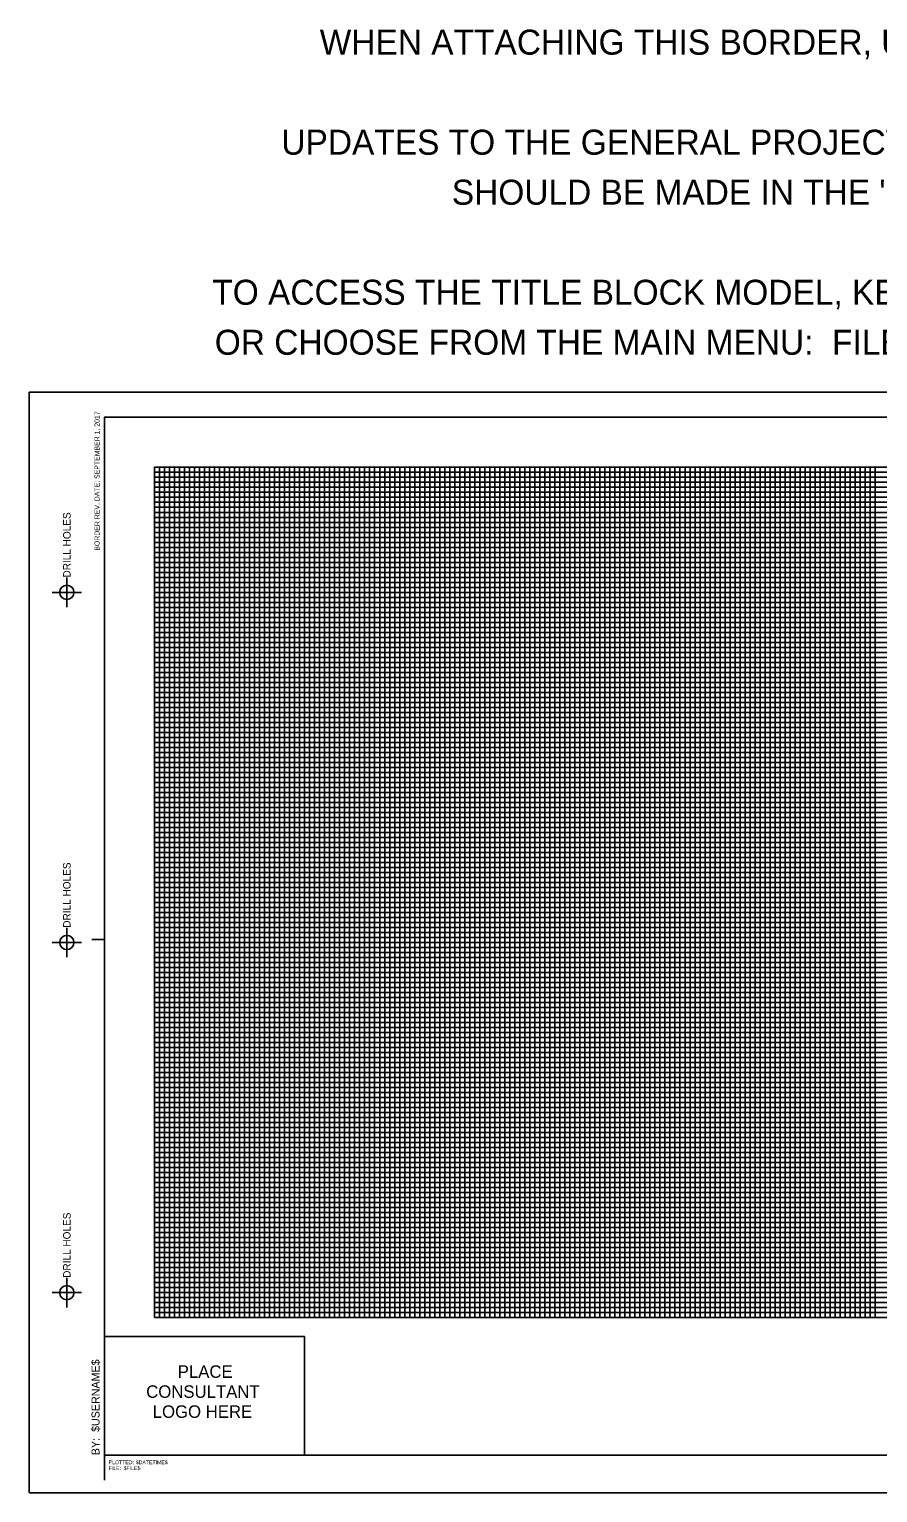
# Model space of a CAD drawing. Extents: x 0 to 34, y 0 to 29.3.
# Drawn here: x 0 to 16.95, y 0 to 29.26 of the extents above; entities that cross this region are included whole.
import ezdxf

# ---------------------------------------------------------------- set-up
doc = ezdxf.new("R2010")
doc.units = 0
for name, color, linetype in [('G-BORD-LINE', 7, 'Continuous'), ('G-CONS-LINE', 7, 'Continuous'), ('G-CONS-LOGO', 7, 'Continuous'), ('G-GRID-MAJR', 7, 'Continuous'), ('G-GRID-MINR', 7, 'Continuous'), ('G-TTLB-TEXT', 7, 'Continuous'), ('G-USER-PAGE', 7, 'Continuous'), ('G-USER-TEXT', 7, 'Continuous')]:
    doc.layers.add(name, color=color, linetype=linetype)

msp = doc.modelspace()

# ---------------------------------------------------------------- linework, layer by layer
at = {"layer": 'G-BORD-LINE'}
for p, q in [((33.5, 21.5), (1.5, 21.5)), ((1.5, 21.5), (1.5, 0.75)), ((1.5, 11.062), (1.25, 11.062)), ((1.5, 0.75), (33.5, 0.75)), ((1.5, 0.75), (1.5, 0.25))]:
    msp.add_line(p, q, dxfattribs=at)
msp.add_lwpolyline([(1.5, 0.75), (33.5, 0.75), (33.5, 21.5), (1.5, 21.5)], close=True, dxfattribs=at)
at = {"layer": 'G-CONS-LINE'}
for p, q in [((1.5, 3.125), (5.5, 3.125)), ((5.5, 3.125), (5.5, 0.75))]:
    msp.add_line(p, q, dxfattribs=at)
at = {"layer": 'G-GRID-MAJR'}
for p, q in [((2.5, 20.5), (2.5, 3.5)), ((32.5, 20.5), (2.5, 20.5)), ((3.5, 20.5), (3.5, 3.5)), ((4.5, 20.5), (4.5, 3.5)), ((5.5, 20.5), (5.5, 3.5)), ((6.5, 20.5), (6.5, 3.5)), ((7.5, 20.5), (7.5, 3.5)), ((8.5, 20.5), (8.5, 3.5)), ((9.5, 20.5), (9.5, 3.5)), ((10.5, 20.5), (10.5, 3.5)), ((11.5, 20.5), (11.5, 3.5)), ((12.5, 20.5), (12.5, 3.5)), ((13.5, 20.5), (13.5, 3.5)), ((14.5, 20.5), (14.5, 3.5)), ((15.5, 20.5), (15.5, 3.5)), ((16.5, 20.5), (16.5, 3.5)), ((32.5, 19.5), (2.5, 19.5)), ((32.5, 18.5), (2.5, 18.5)), ((32.5, 17.5), (2.5, 17.5)), ((32.5, 16.5), (2.5, 16.5)), ((32.5, 15.5), (2.5, 15.5)), ((32.5, 14.5), (2.5, 14.5)), ((32.5, 13.5), (2.5, 13.5)), ((32.5, 12.5), (2.5, 12.5)), ((32.5, 11.5), (2.5, 11.5)), ((32.5, 10.5), (2.5, 10.5)), ((32.5, 9.5), (2.5, 9.5)), ((32.5, 8.5), (2.5, 8.5)), ((32.5, 7.5), (2.5, 7.5)), ((32.5, 6.5), (2.5, 6.5)), ((32.5, 5.5), (2.5, 5.5)), ((32.5, 4.5), (2.5, 4.5)), ((32.5, 3.5), (2.5, 3.5))]:
    msp.add_line(p, q, dxfattribs=at)
at = {"layer": 'G-GRID-MINR'}
for p, q in [((2.6, 20.5), (2.6, 3.5)), ((2.7, 20.5), (2.7, 3.5)), ((2.8, 20.5), (2.8, 3.5)), ((2.9, 20.5), (2.9, 3.5)), ((3, 20.5), (3, 3.5)), ((3.1, 20.5), (3.1, 3.5)), ((3.2, 20.5), (3.2, 3.5)), ((3.3, 20.5), (3.3, 3.5)), ((3.4, 20.5), (3.4, 3.5)), ((3.6, 20.5), (3.6, 3.5)), ((3.7, 20.5), (3.7, 3.5)), ((3.8, 20.5), (3.8, 3.5)), ((3.9, 20.5), (3.9, 3.5)), ((4, 20.5), (4, 3.5)), ((4.1, 20.5), (4.1, 3.5)), ((4.2, 20.5), (4.2, 3.5)), ((4.3, 20.5), (4.3, 3.5)), ((4.4, 20.5), (4.4, 3.5)), ((4.6, 20.5), (4.6, 3.5)), ((4.7, 20.5), (4.7, 3.5)), ((4.8, 20.5), (4.8, 3.5)), ((4.9, 20.5), (4.9, 3.5)), ((5, 20.5), (5, 3.5)), ((5.1, 20.5), (5.1, 3.5)), ((5.2, 20.5), (5.2, 3.5)), ((5.3, 20.5), (5.3, 3.5)), ((5.4, 20.5), (5.4, 3.5)), ((5.6, 20.5), (5.6, 3.5)), ((5.7, 20.5), (5.7, 3.5)), ((5.8, 20.5), (5.8, 3.5)), ((5.9, 20.5), (5.9, 3.5)), ((6, 20.5), (6, 3.5)), ((6.1, 20.5), (6.1, 3.5)), ((6.2, 20.5), (6.2, 3.5)), ((6.3, 20.5), (6.3, 3.5)), ((6.4, 20.5), (6.4, 3.5)), ((6.6, 20.5), (6.6, 3.5)), ((6.7, 20.5), (6.7, 3.5)), ((6.8, 20.5), (6.8, 3.5)), ((6.9, 20.5), (6.9, 3.5)), ((7, 20.5), (7, 3.5)), ((7.1, 20.5), (7.1, 3.5)), ((7.2, 20.5), (7.2, 3.5)), ((7.3, 20.5), (7.3, 3.5)), ((7.4, 20.5), (7.4, 3.5)), ((7.6, 20.5), (7.6, 3.5)), ((7.7, 20.5), (7.7, 3.5)), ((7.8, 20.5), (7.8, 3.5)), ((7.9, 20.5), (7.9, 3.5)), ((8, 20.5), (8, 3.5)), ((8.1, 20.5), (8.1, 3.5)), ((8.2, 20.5), (8.2, 3.5)), ((8.3, 20.5), (8.3, 3.5)), ((8.4, 20.5), (8.4, 3.5)), ((8.6, 20.5), (8.6, 3.5)), ((8.7, 20.5), (8.7, 3.5)), ((8.8, 20.5), (8.8, 3.5)), ((8.9, 20.5), (8.9, 3.5)), ((9, 20.5), (9, 3.5)), ((9.1, 20.5), (9.1, 3.5)), ((9.2, 20.5), (9.2, 3.5)), ((9.3, 20.5), (9.3, 3.5)), ((9.4, 20.5), (9.4, 3.5)), ((9.6, 20.5), (9.6, 3.5)), ((9.7, 20.5), (9.7, 3.5)), ((9.8, 20.5), (9.8, 3.5)), ((9.9, 20.5), (9.9, 3.5)), ((10, 20.5), (10, 3.5)), ((10.1, 20.5), (10.1, 3.5)), ((10.2, 20.5), (10.2, 3.5)), ((10.3, 20.5), (10.3, 3.5)), ((10.4, 20.5), (10.4, 3.5)), ((10.6, 20.5), (10.6, 3.5)), ((10.7, 20.5), (10.7, 3.5)), ((10.8, 20.5), (10.8, 3.5)), ((10.9, 20.5), (10.9, 3.5)), ((11, 20.5), (11, 3.5)), ((11.1, 20.5), (11.1, 3.5)), ((11.2, 20.5), (11.2, 3.5)), ((11.3, 20.5), (11.3, 3.5)), ((11.4, 20.5), (11.4, 3.5)), ((11.6, 20.5), (11.6, 3.5)), ((11.7, 20.5), (11.7, 3.5)), ((11.8, 20.5), (11.8, 3.5)), ((11.9, 20.5), (11.9, 3.5)), ((12, 20.5), (12, 3.5)), ((12.1, 20.5), (12.1, 3.5)), ((12.2, 20.5), (12.2, 3.5)), ((12.3, 20.5), (12.3, 3.5)), ((12.4, 20.5), (12.4, 3.5)), ((12.6, 20.5), (12.6, 3.5)), ((12.7, 20.5), (12.7, 3.5)), ((12.8, 20.5), (12.8, 3.5)), ((12.9, 20.5), (12.9, 3.5)), ((13, 20.5), (13, 3.5)), ((13.1, 20.5), (13.1, 3.5)), ((13.2, 20.5), (13.2, 3.5)), ((13.3, 20.5), (13.3, 3.5)), ((13.4, 20.5), (13.4, 3.5)), ((13.6, 20.5), (13.6, 3.5)), ((13.7, 20.5), (13.7, 3.5)), ((13.8, 20.5), (13.8, 3.5)), ((13.9, 20.5), (13.9, 3.5)), ((14, 20.5), (14, 3.5)), ((14.1, 20.5), (14.1, 3.5)), ((14.2, 20.5), (14.2, 3.5)), ((14.3, 20.5), (14.3, 3.5)), ((14.4, 20.5), (14.4, 3.5)), ((14.6, 20.5), (14.6, 3.5)), ((14.7, 20.5), (14.7, 3.5)), ((14.8, 20.5), (14.8, 3.5)), ((14.9, 20.5), (14.9, 3.5)), ((15, 20.5), (15, 3.5)), ((15.1, 20.5), (15.1, 3.5)), ((15.2, 20.5), (15.2, 3.5)), ((15.3, 20.5), (15.3, 3.5)), ((15.4, 20.5), (15.4, 3.5)), ((15.6, 20.5), (15.6, 3.5)), ((15.7, 20.5), (15.7, 3.5)), ((15.8, 20.5), (15.8, 3.5)), ((15.9, 20.5), (15.9, 3.5)), ((16, 20.5), (16, 3.5)), ((16.1, 20.5), (16.1, 3.5)), ((16.2, 20.5), (16.2, 3.5)), ((16.3, 20.5), (16.3, 3.5)), ((16.4, 20.5), (16.4, 3.5)), ((16.6, 20.5), (16.6, 3.5)), ((16.7, 20.5), (16.7, 3.5)), ((16.8, 20.5), (16.8, 3.5)), ((16.9, 20.5), (16.9, 3.5)), ((32.5, 20.4), (2.5, 20.4)), ((32.5, 20.3), (2.5, 20.3)), ((32.5, 20.2), (2.5, 20.2)), ((32.5, 20.1), (2.5, 20.1)), ((32.5, 20), (2.5, 20)), ((32.5, 19.9), (2.5, 19.9)), ((32.5, 19.8), (2.5, 19.8)), ((32.5, 19.7), (2.5, 19.7)), ((32.5, 19.6), (2.5, 19.6)), ((32.5, 19.4), (2.5, 19.4)), ((32.5, 19.3), (2.5, 19.3)), ((32.5, 19.2), (2.5, 19.2)), ((32.5, 19.1), (2.5, 19.1)), ((32.5, 19), (2.5, 19)), ((32.5, 18.9), (2.5, 18.9)), ((32.5, 18.8), (2.5, 18.8)), ((32.5, 18.7), (2.5, 18.7)), ((32.5, 18.6), (2.5, 18.6)), ((32.5, 18.4), (2.5, 18.4)), ((32.5, 18.3), (2.5, 18.3)), ((32.5, 18.2), (2.5, 18.2)), ((32.5, 18.1), (2.5, 18.1)), ((32.5, 18), (2.5, 18)), ((32.5, 17.9), (2.5, 17.9)), ((32.5, 17.8), (2.5, 17.8)), ((32.5, 17.7), (2.5, 17.7)), ((32.5, 17.6), (2.5, 17.6)), ((32.5, 17.4), (2.5, 17.4)), ((32.5, 17.3), (2.5, 17.3)), ((32.5, 17.2), (2.5, 17.2)), ((32.5, 17.1), (2.5, 17.1)), ((32.5, 17), (2.5, 17)), ((32.5, 16.9), (2.5, 16.9)), ((32.5, 16.8), (2.5, 16.8)), ((32.5, 16.7), (2.5, 16.7)), ((32.5, 16.6), (2.5, 16.6)), ((32.5, 16.4), (2.5, 16.4)), ((32.5, 16.3), (2.5, 16.3)), ((32.5, 16.2), (2.5, 16.2)), ((32.5, 16.1), (2.5, 16.1)), ((32.5, 16), (2.5, 16)), ((32.5, 15.9), (2.5, 15.9)), ((32.5, 15.8), (2.5, 15.8)), ((32.5, 15.7), (2.5, 15.7)), ((32.5, 15.6), (2.5, 15.6)), ((32.5, 15.4), (2.5, 15.4)), ((32.5, 15.3), (2.5, 15.3)), ((32.5, 15.2), (2.5, 15.2)), ((32.5, 15.1), (2.5, 15.1)), ((32.5, 15), (2.5, 15)), ((32.5, 14.9), (2.5, 14.9)), ((32.5, 14.8), (2.5, 14.8)), ((32.5, 14.7), (2.5, 14.7)), ((32.5, 14.6), (2.5, 14.6)), ((32.5, 14.4), (2.5, 14.4)), ((32.5, 14.3), (2.5, 14.3)), ((32.5, 14.2), (2.5, 14.2)), ((32.5, 14.1), (2.5, 14.1)), ((32.5, 14), (2.5, 14)), ((32.5, 13.9), (2.5, 13.9)), ((32.5, 13.8), (2.5, 13.8)), ((32.5, 13.7), (2.5, 13.7)), ((32.5, 13.6), (2.5, 13.6)), ((32.5, 13.4), (2.5, 13.4)), ((32.5, 13.3), (2.5, 13.3)), ((32.5, 13.2), (2.5, 13.2)), ((32.5, 13.1), (2.5, 13.1)), ((32.5, 13), (2.5, 13)), ((32.5, 12.9), (2.5, 12.9)), ((32.5, 12.8), (2.5, 12.8)), ((32.5, 12.7), (2.5, 12.7)), ((32.5, 12.6), (2.5, 12.6)), ((32.5, 12.4), (2.5, 12.4)), ((32.5, 12.3), (2.5, 12.3)), ((32.5, 12.2), (2.5, 12.2)), ((32.5, 12.1), (2.5, 12.1)), ((32.5, 12), (2.5, 12)), ((32.5, 11.9), (2.5, 11.9)), ((32.5, 11.8), (2.5, 11.8)), ((32.5, 11.7), (2.5, 11.7)), ((32.5, 11.6), (2.5, 11.6)), ((32.5, 11.4), (2.5, 11.4)), ((32.5, 11.3), (2.5, 11.3)), ((32.5, 11.2), (2.5, 11.2)), ((32.5, 11.1), (2.5, 11.1)), ((32.5, 11), (2.5, 11)), ((32.5, 10.9), (2.5, 10.9)), ((32.5, 10.8), (2.5, 10.8)), ((32.5, 10.7), (2.5, 10.7)), ((32.5, 10.6), (2.5, 10.6)), ((32.5, 10.4), (2.5, 10.4)), ((32.5, 10.3), (2.5, 10.3)), ((32.5, 10.2), (2.5, 10.2)), ((32.5, 10.1), (2.5, 10.1)), ((32.5, 10), (2.5, 10)), ((32.5, 9.9), (2.5, 9.9)), ((32.5, 9.8), (2.5, 9.8)), ((32.5, 9.7), (2.5, 9.7)), ((32.5, 9.6), (2.5, 9.6)), ((32.5, 9.4), (2.5, 9.4)), ((32.5, 9.3), (2.5, 9.3)), ((32.5, 9.2), (2.5, 9.2)), ((32.5, 9.1), (2.5, 9.1)), ((32.5, 9), (2.5, 9)), ((32.5, 8.9), (2.5, 8.9)), ((32.5, 8.8), (2.5, 8.8)), ((32.5, 8.7), (2.5, 8.7)), ((32.5, 8.6), (2.5, 8.6)), ((32.5, 8.4), (2.5, 8.4)), ((32.5, 8.3), (2.5, 8.3)), ((32.5, 8.2), (2.5, 8.2)), ((32.5, 8.1), (2.5, 8.1)), ((32.5, 8), (2.5, 8)), ((32.5, 7.9), (2.5, 7.9)), ((32.5, 7.8), (2.5, 7.8)), ((32.5, 7.7), (2.5, 7.7)), ((32.5, 7.6), (2.5, 7.6)), ((32.5, 7.4), (2.5, 7.4)), ((32.5, 7.3), (2.5, 7.3)), ((32.5, 7.2), (2.5, 7.2)), ((32.5, 7.1), (2.5, 7.1)), ((32.5, 7), (2.5, 7)), ((32.5, 6.9), (2.5, 6.9)), ((32.5, 6.8), (2.5, 6.8)), ((32.5, 6.7), (2.5, 6.7)), ((32.5, 6.6), (2.5, 6.6)), ((32.5, 6.4), (2.5, 6.4)), ((32.5, 6.3), (2.5, 6.3)), ((32.5, 6.2), (2.5, 6.2)), ((32.5, 6.1), (2.5, 6.1)), ((32.5, 6), (2.5, 6)), ((32.5, 5.9), (2.5, 5.9)), ((32.5, 5.8), (2.5, 5.8)), ((32.5, 5.7), (2.5, 5.7)), ((32.5, 5.6), (2.5, 5.6)), ((32.5, 5.4), (2.5, 5.4)), ((32.5, 5.3), (2.5, 5.3)), ((32.5, 5.2), (2.5, 5.2)), ((32.5, 5.1), (2.5, 5.1)), ((32.5, 5), (2.5, 5)), ((32.5, 4.9), (2.5, 4.9)), ((32.5, 4.8), (2.5, 4.8)), ((32.5, 4.7), (2.5, 4.7)), ((32.5, 4.6), (2.5, 4.6)), ((32.5, 4.4), (2.5, 4.4)), ((32.5, 4.3), (2.5, 4.3)), ((32.5, 4.2), (2.5, 4.2)), ((32.5, 4.1), (2.5, 4.1)), ((32.5, 4), (2.5, 4)), ((32.5, 3.9), (2.5, 3.9)), ((32.5, 3.8), (2.5, 3.8)), ((32.5, 3.7), (2.5, 3.7)), ((32.5, 3.6), (2.5, 3.6))]:
    msp.add_line(p, q, dxfattribs=at)
at = {"layer": 'G-TTLB-TEXT'}
for p, q in [((0.75, 18.296), (0.75, 18)), ((0.454, 18), (1.046, 18)), ((0.75, 18), (0.75, 17.704)), ((0.75, 11.296), (0.75, 11)), ((1.046, 11), (0.454, 11)), ((0.75, 11), (0.75, 10.704)), ((0.75, 4.296), (0.75, 3.704)), ((0.454, 4), (1.046, 4))]:
    msp.add_line(p, q, dxfattribs=at)
for centre in [(0.75, 18), (0.75, 11), (0.75, 4)]:
    msp.add_circle(centre, 0.143, dxfattribs=at)
at = {"layer": 'G-USER-PAGE'}
msp.add_lwpolyline([(0, 22), (34, 22), (34, 0), (0, 0)], close=True, dxfattribs=at)

# ---------------------------------------------------------------- texts
at = {"layer": 'G-CONS-LOGO'}
for s, p in [('PLACE', (2.966, 2.297)), ('CONSULTANT', (2.336, 1.897)), ('LOGO HERE', (2.466, 1.497))]:
    msp.add_text(s, height=0.25, dxfattribs=at).set_placement(p)
at = {"layer": 'G-TTLB-TEXT'}
for s, height, rotation, p in [('$USERNAME$', 0.16, 90, (1.403, 1.215)), ('BY:', 0.16, 90, (1.403, 0.75)), ('PLOTTED:', 0.075, 360, (1.586, 0.57)), ('$DATETIME$', 0.075, 360, (2.127, 0.57)), ('FILE:', 0.075, 360, (1.586, 0.455)), ('$FILE$', 0.075, 360, (1.885, 0.455))]:
    msp.add_text(s, height=height, rotation=rotation, dxfattribs=at).set_placement(p)
at = {"layer": 'G-USER-TEXT'}
for s, p in [('WHEN ATTACHING THIS BORDER, USE "LIVE NESTING DEPTH 1".', (5.802, 28.75)), ('UPDATES TO THE GENERAL PROJECT INFORMATION IN THIS BORDER', (5.036, 26.75)), ('SHOULD BE MADE IN THE "TITLE BLOCK" MODEL', (8.441, 25.75)), ('TO ACCESS THE TITLE BLOCK MODEL, KEY-IN:  MODEL ACTIVE="TITLE BLOCK"', (3.656, 23.75)), ('OR CHOOSE FROM THE MAIN MENU:  FILE >MODELS >TITLE BLOCK MODEL', (3.705, 22.75))]:
    msp.add_text(s, height=0.5, dxfattribs=at).set_placement(p)
for s, height, p in [('BORDER REV. DATE: SEPTEMBER 1, 2017', 0.1, (1.403, 18.833)), ('DRILL HOLES', 0.15, (0.825, 18.296)), ('DRILL HOLES', 0.15, (0.825, 11.296)), ('DRILL HOLES', 0.15, (0.825, 4.296))]:
    msp.add_text(s, height=height, rotation=90, dxfattribs=at).set_placement(p)

doc.saveas('drawing.dxf')
